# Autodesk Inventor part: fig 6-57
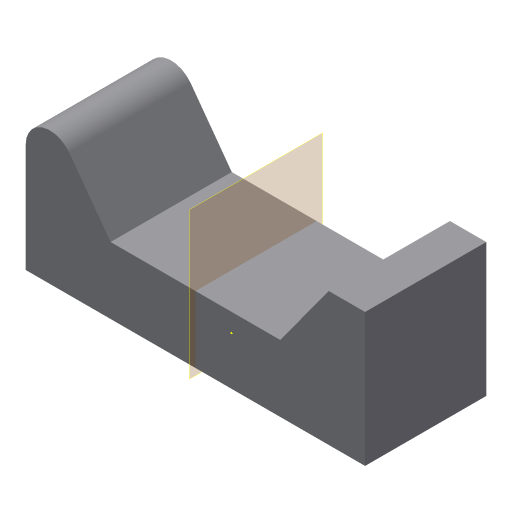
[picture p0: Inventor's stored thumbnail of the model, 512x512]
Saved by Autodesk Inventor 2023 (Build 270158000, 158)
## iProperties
Created: 2011-07
Part Number: fig 6-57
Material: Generic
Document SubType Name: Modeling
Designer: CadCim
Density: 1 g/cm^3
Appearance: Default
Author: CadCim
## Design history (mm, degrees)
sketch "Sketch1"
  geometry: 1 further point
sketch "Sketch2"
  geometry: L1 (3, -4)-(17, -4); L2 (17, -4)-(17, 7); L3 (17, 7)-(14, 7); L4 (14, 7)-(10, 1.5); L5 (10, 1.5)-(3, 1.5); L6 (3, -4)-(-11, -4); L7 (-11, -4)-(-11, 7); L8 (-11, 7)-(-8, 7); L9 (-8, 7)-(-4, 1.5); L10 (-4, 1.5)-(3, 1.5); 1 further point
  constraints: 20 end point, 2 parallel, 1 perpendicular
extrude "Extrusion1" new body sketch "Sketch2" distance "d0" = 10; taper "d1" = 0 deg
fillet "Fillet1" dims "d2" = 2
workplane "Work Plane1"
body "Solid1"
